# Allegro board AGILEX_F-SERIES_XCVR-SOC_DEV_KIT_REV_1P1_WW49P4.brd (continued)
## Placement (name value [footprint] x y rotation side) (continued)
C966  DNI  [7343-V_LOW-PROFILE]  51.92 195.07 270 bottom
C967  47uF  [7343-V_LOW-PROFILE]  46.71 195.2 270 top
C968  47uF  [7343-V_LOW-PROFILE]  59.16 195.33 270 top
C969  47uF  [7343-V_LOW-PROFILE]  56.84 211.96 90 top
C970  0.022uF  [0402]  50.26 192.53 90 top
C976  100uF  [1206]  215.26 183.82 270 top
C977  100uF  [1206]  212.29 183.82 270 top
C978  100uF  [1206]  215.32 183.85 270 bottom
C979  100uF  [1206]  215.65 195.2 90 top
C980  100uF  [1206]  198.09 185.85 270 bottom
C981  100uF  [1206]  201.17 185.04 0 top
C982  100uF  [1206]  191.41 197.41 90 top
C983  100uF  [1206]  194.28 197.38 90 top
C984  470uF  [7343P]  214.4 196.27 90 bottom
C985  470uF  [7343P]  191.72 197.03 90 bottom
C986  1uF  [0603]  43.36 23.75 0 top
C987  DNI  [0402]  191.13 188.09 0 bottom
C988  2.2uF  [0402]  195.71 198.58 90 bottom
C989  22uF  [1206]  201.68 209.93 0 bottom
C990  22uF  [1206]  207.04 210.69 180 top
C991  22uF  [1206]  201.42 206.58 0 bottom
C992  22uF  [1206]  207.52 204.85 180 bottom
C993  22uF  [1206]  207.52 207.65 180 top
C994  22uF  [1206]  201.29 213.11 0 bottom
C995  22uF  [1206]  207.52 207.65 180 bottom
C1094  100uF  [1206]  191.95 129.41 90 top
C1095  100uF  [1206]  196.95 118.41 270 top
C1096  100uF  [1206]  196.95 118.44 270 bottom
C1097  100uF  [1206]  215.75 118.26 270 bottom
C1098  100uF  [1206]  214.25 129.69 90 top
C1099  100uF  [1206]  212.5 118.29 270 top
C1100  100uF  [1206]  215.72 118.29 270 top
C1101  100uF  [1206]  188.93 129.44 90 top
C1102  470uF  [7343P]  193.57 129.9 90 bottom
C1103  470uF  [7343P]  214.05 130.68 90 bottom
C1104  1uF  [0402]  121.03 111.38 180 bottom
C1105  DNI  [0402]  189.92 122.89 0 bottom
C1107  22uF  [1206]  200.41 144.42 0 bottom
C1108  22uF  [1206]  206.12 139.34 180 bottom
C1109  22uF  [1206]  206.4 145.19 180 top
C1110  22uF  [1206]  200.41 147.83 0 bottom
C1111  22uF  [1206]  206.4 147.83 180 top
C1112  22uF  [1206]  200.41 141.07 0 bottom
C1113  22uF  [1206]  206.4 142.14 180 top
C1116  100uF  [1206]  209.91 153.62 180 bottom
C1117  100uF  [1206]  209.91 156.46 180 top
C1118  100uF  [1206]  209.91 156.46 180 bottom
C1119  100uF  [1206]  209.75 175.67 180 top
C1120  100uF  [1206]  209.91 153.62 180 top
C1121  100uF  [1206]  209.75 175.67 180 bottom
C1122  1uF  [0402]  110.34 118.36 270 bottom
C1123  100uF  [1206]  209.75 178.49 180 bottom
C1124  100uF  [1206]  209.75 178.49 180 top
C1125  DNI  [0402]  193.55 158.93 0 bottom
C1129  150uF  [7343P]  201.55 179.91 0 bottom
C1130  22uF  [1206]  201.5 175.64 180 top
C1131  22uF  [1206]  201.5 175.64 180 bottom
C1132  22uF  [1206]  201.47 153.64 180 top
C1133  22uF  [1206]  201.52 178.56 180 top
C1136  100uF  [1206]  31.65 25.98 0 top
C1137  10uF  [0402]  31.5 28.45 270 top
C1138  22uF  [0603]  23.88 31.37 0 bottom
C1140  150uF  [7343P]  23.62 27.3 0 bottom
C1141  150uF  [7343P]  23.67 27.36 0 top
C1145  100uF  [1206]  125.09 13.87 270 top
C1146  10uF  [0402]  127.3 13.82 180 top
C1148  22uF  [0603]  129.26 21.84 270 bottom
C1149  150uF  [7343P]  125.2 21.67 270 bottom
C1150  150uF  [7343P]  125.22 21.67 270 top
C1154  100uF  [1206]  14.15 29.13 0 top
C1155  10uF  [0402]  14.12 31.52 270 top
C1156  22uF  [0603]  6.48 34.42 0 bottom
C1157  150uF  [7343P]  6.22 30.35 0 top
C1158  150uF  [7343P]  6.22 30.35 0 bottom
C1169  100uF  [1206]  49.05 28.27 0 top
C1170  10uF  [0402]  48.77 30.61 270 top
C1171  22uF  [0603]  41.15 33.53 0 bottom
C1172  150uF  [7343P]  40.89 29.41 0 top
C1173  150uF  [7343P]  40.89 29.46 0 bottom
C1178  10uF  [0603]  62.1 145.41 180 top
C1179  10uF  [0603]  62.1 143 180 top
C1181  47uF  [0603]  60.43 133.68 0 top
C1182  47uF  [0603]  60.41 135.87 0 top
C1184  47uF  [0603]  52.73 49.15 270 top
C1185  10uF  [0603]  57.73 42.62 0 top
C1186  47uF  [0603]  55.14 49.15 270 top
C1187  10uF  [0603]  57.73 45.16 0 top
C1199  100uF  [1206]  100.18 13.92 270 top
C1200  10uF  [0402]  102.41 14.22 180 top
C1201  22uF  [0603]  104.52 21.84 270 bottom
C1202  150uF  [7343P]  100.46 21.79 270 bottom
C1203  150uF  [7343P]  100.46 21.79 270 top
C1217  100uF  [1206]  148.29 13.74 270 top
C1218  10uF  [0402]  150.55 13.77 180 top
C1219  22uF  [0603]  152.5 21.84 270 bottom
C1220  150uF  [7343P]  148.44 21.72 270 bottom
C1221  150uF  [7343P]  148.46 21.72 270 top
C1226  100uF  [1206]  80.59 14.12 270 top
C1227  10uF  [0402]  82.63 14.07 180 top
C1228  22uF  [0603]  84.38 21.84 270 bottom
C1229  150uF  [7343P]  80.26 22.1 270 top
C1230  150uF  [7343P]  80.31 22.1 270 bottom
C1237  47uF  [0603]  39.52 11.73 270 top
C1238  47uF  [0603]  37.34 11.81 270 top
C1290  DNI  [1206]  70.87 116.71 180 bottom
C1291  DNI  [1206]  70.87 113.92 180 bottom
C1292  DNI  [1206]  105.52 132.13 90 bottom
C1293  DNI  [1206]  102.72 132.13 90 bottom
C1294  DNI  [1206]  137.51 132.97 90 bottom
C1295  DNI  [1206]  134.72 132.97 90 bottom
C1296  22uF  [0603]  147.17 120.27 180 bottom
C1297  22uF  [0603]  147.17 117.98 180 bottom
C1298  22uF  [0603]  147.17 124.84 180 bottom
C1299  22uF  [0603]  147.17 122.55 180 bottom
C1300  22uF  [0603]  136.25 125.35 270 bottom
C1301  22uF  [0603]  138.15 125.35 270 bottom
C1302  22uF  [0603]  71.75 125.22 0 bottom
C1303  22uF  [0603]  71.75 123.19 0 bottom
C1304  22uF  [0603]  71.75 119.13 0 bottom
C1305  22uF  [0603]  71.75 121.16 0 bottom
C1306  22uF  [0603]  93.22 126.62 270 bottom
C1307  22uF  [0603]  91.19 126.62 270 bottom
C1308  22uF  [0603]  89.15 126.62 270 bottom
C1309  22uF  [0603]  87.12 126.62 270 bottom
C1310  22uF  [0603]  85.09 126.62 270 bottom
C1316  DNI  [2012]  80.74 93.1 0 bottom
C1317  DNI  [2012]  80.74 89.6 0 bottom
C1318  DNI  [2012]  80.74 91.35 0 bottom
C1319  4.7uF  [0603]  122.15 76.07 270 bottom
C1325  DNI  [0402]  132.52 7.18 180 bottom
C1326  DNI  [0402]  131.64 7.18 180 bottom
C1327  DNI  [0402]  185.83 63.24 0 bottom
C1328  0.1uF  [0402]  166.5 42.67 90 bottom
C1329  1uF  [0402]  166.5 43.69 90 bottom
C1330  0.1uF  [0402]  166.27 45.36 0 bottom
C1331  0.1uF  [0402]  185.39 51.94 0 bottom
C1332  0.1uF  [0402]  177.9 72.77 90 top
C1333  10uF  [C0805]  172.18 75.37 180 top
C1334  10uF  [C0805]  174.6 75.37 180 top
C1335  0.1uF  [0402]  170.53 74.87 0 top
C1336  0.1uF  [0402]  172.06 60.07 270 top
C1337  DNI  [0201]  104.83 95.85 30 bottom
C1338  DNI  [0201]  119.55 103.35 210 bottom
C1339  DNI  [0201]  111.76 95.85 30 bottom
C1340  DNI  [0201]  103.1 104.85 30 bottom
C1341  DNI  [0201]  103.1 103.85 30 bottom
C1342  DNI  [0201]  103.1 102.85 30 bottom
C1343  DNI  [0201]  103.1 101.85 30 bottom
C1344  DNI  [0201]  117.82 107.35 210 bottom
C1345  DNI  [0201]  112.63 107.35 210 bottom
C1346  DNI  [0201]  116.09 107.35 210 bottom
C1347  DNI  [0201]  107.43 94.35 210 bottom
C1348  DNI  [0201]  120.42 109.85 30 bottom
C1349  DNI  [0201]  114.36 96.35 210 bottom
C1350  DNI  [0201]  103.1 105.85 30 bottom
C1351  DNI  [0201]  104.83 99.85 30 bottom
C1352  DNI  [0201]  104.83 101.85 30 bottom
C1353  DNI  [0201]  104.83 103.85 30 bottom
C1354  DNI  [0201]  104.83 105.85 30 bottom
C1355  DNI  [0201]  102.23 107.35 210 bottom
C1356  DNI  [0201]  110.03 95.85 30 bottom
C1357  DNI  [0201]  103.1 106.85 30 bottom
C1358  DNI  [0201]  107.43 107.35 210 bottom
C1359  DNI  [0201]  103.1 94.85 30 bottom
C1360  DNI  [0201]  109.16 107.35 210 bottom
C1361  DNI  [0201]  103.1 100.85 30 bottom
C1362  DNI  [0201]  103.1 97.85 30 bottom
C1363  DNI  [0201]  103.1 99.85 30 bottom
C1364  DNI  [0201]  103.1 96.85 30 bottom
C1365  DNI  [0201]  103.97 94.35 210 bottom
C1366  DNI  [0201]  104.83 97.85 30 bottom
C1367  DNI  [0201]  119.55 97.35 210 bottom
C1368  DNI  [0201]  119.55 98.35 210 bottom
C1369  DNI  [0201]  119.55 99.35 210 bottom
C1370  DNI  [0201]  119.55 100.35 210 bottom
C1371  DNI  [0201]  119.55 101.35 210 bottom
C1372  DNI  [0201]  119.55 102.35 210 bottom
C1373  DNI  [0201]  119.55 104.35 210 bottom
C1374  DNI  [0201]  119.55 105.35 210 bottom
C1375  DNI  [0201]  119.55 106.35 210 bottom
C1376  DNI  [0201]  119.55 107.35 210 bottom
C1377  1uF  [0201]  100.08 104.65 270 bottom
C1378  10uF  [0603]  97.13 75.06 90 bottom
C1379  10uF  [0603]  103.64 125.22 270 bottom
C1380  10uF  [0603]  106.78 125.22 270 bottom
C1381  4.7uF  [0201]  107.43 110.85 150 bottom
C1382  4.7uF  [0201]  107.43 92.35 210 bottom
C1383  4.7uF  [0201]  110.03 111.35 330 bottom
C1384  4.7uF  [0201]  110.89 110.35 210 bottom
C1385  1uF  [0201]  116.09 92.35 210 bottom
C1386  4.7uF  [0201]  109.16 92.35 210 bottom
C1387  4.7uF  [0201]  110.03 91.85 30 bottom
C1388  1uF  [0201]  111.76 91.85 30 bottom
C1389  10uF  [0603]  102.84 74.93 90 bottom
C1390  0.1uF  [0402]  184.33 170.47 180 bottom
C1391  0.1uF  [0402]  185.6 170.47 180 bottom
C1392  0.1uF  [0402]  186.87 170.47 180 bottom
C1393  0.1uF  [0402]  188.14 170.47 180 bottom
C1394  0.1uF  [0402]  189.41 170.47 180 bottom
C1395  0.1uF  [0402]  190.68 170.47 180 bottom
C1396  0.1uF  [0402]  191.95 170.47 180 bottom
C1397  0.1uF  [0402]  193.22 170.47 180 bottom
C1398  0.1uF  [0402]  138.18 194.94 0 bottom
C1399  0.1uF  [0402]  142.62 194.94 0 bottom
C1400  0.1uF  [0402]  147.07 194.94 0 bottom
C1401  0.1uF  [0402]  151.36 194.88 0 bottom
C1402  0.1uF  [0402]  155.96 194.94 0 bottom
C1403  0.1uF  [0402]  160.4 194.94 0 bottom
C1404  0.1uF  [0402]  164.85 194.94 0 bottom
C1405  0.1uF  [0402]  169.16 194.94 0 bottom
C1408  DNI  [0402]  30.71 188.47 90 bottom
C1409  0.1uF  [0402]  33.75 153.42 90 bottom
C1410  0.1uF  [0402]  163.17 125.86 90 top
C1411  0.1uF  [0402]  163.17 127.13 90 top
C1412  10uF  [0603]  33.86 156.01 270 top
C1413  0.1uF  [0402]  35.63 157.76 180 top
C1414  0.1uF  [0402]  36.65 157.76 180 top
C1415  10uF  [0603]  59.2 150.16 90 top
C1416  0.1uF  [0402]  56.64 147.52 0 top
C1417  0.1uF  [0402]  57.68 147.52 0 top
C1424  22uF  [0805]  148.84 93.85 180 bottom
C1425  47uF  [0805]  151.38 93.85 180 bottom
C1426  100uF  [0805]  154.31 93.85 180 bottom
C1427  1uF  [0402]  113.59 60.22 90 bottom
C1428  1uF  [0402]  127.23 55.12 0 bottom
C1429  1uF  [0402]  115.42 59.89 180 bottom
C1430  1uF  [0402]  126.29 63.19 0 bottom
C1431  1uF  [0402]  129 51.55 180 bottom
C1432  1uF  [0402]  124.51 63.32 0 bottom
C1433  1uF  [0402]  124.69 55.12 0 bottom
C1434  1uF  [0402]  129.08 63.22 0 bottom
C1435  1uF  [0402]  127.84 63.22 0 bottom
C1436  1uF  [0402]  123.04 63.32 0 bottom
C1437  1uF  [0402]  121.79 63.32 0 bottom
C1438  1uF  [0402]  118.64 59.79 180 bottom
C1439  1uF  [0402]  116.89 59.89 180 bottom
C1440  1uF  [0402]  118.21 51.05 180 bottom
C1441  47uF  [0805]  126.06 46.99 180 bottom
C1442  47uF  [0805]  103.88 46.79 180 bottom
C1443  47uF  [0805]  108.58 46.79 180 bottom
C1444  47uF  [0805]  106.17 46.79 180 bottom
C1445  47uF  [0805]  119.48 46.99 180 bottom
C1446  47uF  [0805]  111 46.79 180 bottom
C1447  47uF  [0805]  121.64 46.99 180 bottom
C1448  47uF  [0805]  117.45 46.99 180 bottom
C1457  1uF  [0402]  91.29 50.8 270 bottom
C1458  1uF  [0402]  91.29 49.66 270 bottom
C1461  47uF  [0805]  87.35 51.69 0 bottom
C1463  2.2uF  [0402]  90.4 61.09 270 bottom
C1466  1uF  [0402]  84.35 60.83 90 bottom
C1468  1uF  [0402]  102.71 143.32 90 bottom
C1469  1uF  [0402]  103.18 145.24 180 bottom
C1470  1uF  [0402]  103.18 147 180 bottom
C1471  1uF  [0402]  97.89 145.67 90 bottom
C1472  1uF  [0402]  102.78 152.92 90 bottom
C1473  1uF  [0402]  95.48 153.92 90 bottom
C1474  1uF  [0402]  95.98 149.22 180 bottom
C1475  1uF  [0402]  95.91 142.84 180 bottom
C1476  1uF  [0402]  91.36 143.32 90 bottom
C1477  1uF  [0402]  91.76 145.24 180 bottom
C1478  1uF  [0402]  91.76 147 180 bottom
C1479  1uF  [0402]  84.09 153.94 90 bottom
C1480  1uF  [0402]  91.36 152.92 90 bottom
C1481  1uF  [0402]  86.53 145.72 90 bottom
C1482  1uF  [0402]  84.55 149.22 180 bottom
C1483  1uF  [0402]  84.55 142.87 180 bottom
C1484  10uF  [0603]  119.23 140.65 180 bottom
C1485  10uF  [0603]  96.43 140.65 180 bottom
C1486  10uF  [0603]  85.03 140.65 180 bottom
C1487  10uF  [0603]  99.78 142.92 270 bottom
C1488  10uF  [0603]  88.27 142.92 270 bottom
C1489  1uF  [0402]  102.74 141.73 90 bottom
C1490  1uF  [0402]  95.48 155.32 90 bottom
C1491  1uF  [0402]  95.48 152.91 90 bottom
C1492  1uF  [0402]  104.78 141.73 270 bottom
C1493  1uF  [0402]  84.05 155.32 90 bottom
C1494  1uF  [0402]  84.09 152.87 90 bottom
C1495  1uF  [0402]  93.34 141.73 270 bottom
C1496  1uF  [0402]  91.31 141.73 90 bottom
C1497  10uF  [0603]  103.51 139.72 0 bottom
C1498  10uF  [0603]  91.91 139.72 0 bottom
C1499  1uF  [0402]  125.63 143.32 90 bottom
C1500  1uF  [0402]  126.08 145.24 180 bottom
C1501  1uF  [0402]  118.85 142.82 180 bottom
C1502  1uF  [0402]  126.08 147 180 bottom
C1503  1uF  [0402]  118.36 149.76 90 bottom
C1504  1uF  [0402]  126.01 153.37 0 bottom
C1505  1uF  [0402]  118.34 147.17 90 bottom
C1506  1uF  [0402]  118.34 153.8 90 bottom
C1507  1uF  [0402]  114.21 152.92 90 bottom
C1508  1uF  [0402]  106.9 147.32 90 bottom
C1509  1uF  [0402]  114.63 147 180 bottom
C1510  1uF  [0402]  114.21 143.32 90 bottom
C1511  1uF  [0402]  114.63 145.24 180 bottom
C1512  1uF  [0402]  107.43 142.84 180 bottom
C1513  1uF  [0402]  107.41 149.22 180 bottom
C1514  1uF  [0402]  106.91 153.8 90 bottom
C1515  10uF  [0603]  122.65 146.81 270 bottom
C1516  10uF  [0603]  122.71 142.92 270 bottom
C1517  10uF  [0603]  111.25 142.92 270 bottom
C1518  10uF  [0603]  110.84 146.81 270 bottom
C1519  10uF  [0603]  107.91 140.65 180 bottom
C1520  1uF  [0402]  127.64 141.73 270 bottom
C1521  1uF  [0402]  125.6 141.73 90 bottom
C1522  1uF  [0402]  118.34 155.32 90 bottom
C1523  1uF  [0402]  118.34 152.78 90 bottom
C1524  1uF  [0402]  106.91 155.32 90 bottom
C1525  1uF  [0402]  106.91 152.78 90 bottom
C1526  1uF  [0402]  114.17 141.73 90 bottom
C1527  1uF  [0402]  116.2 141.73 270 bottom
C1528  10uF  [0603]  125.91 139.72 0 bottom
C1529  10uF  [0603]  114.71 139.97 0 bottom
C1530  1uF  [0402]  80.74 149.1 180 bottom
C1531  1uF  [0402]  73.12 149.22 180 bottom
C1532  1uF  [0402]  74.35 147.32 270 bottom
C1533  1uF  [0402]  80.31 145.22 180 bottom
C1534  1uF  [0402]  79.91 152.92 90 bottom
C1535  1uF  [0402]  72.62 153.8 90 bottom
C1536  1uF  [0402]  75.11 145.72 90 bottom
C1537  1uF  [0402]  80.31 146.97 180 bottom
C1546  10uF  [0603]  71.88 147.7 270 bottom
C1547  10uF  [0603]  72.24 140.08 90 bottom
C1551  1uF  [0402]  81.92 141.73 270 bottom
C1552  1uF  [0402]  79.91 141.72 90 bottom
C1553  1uF  [0402]  69.95 153.54 90 bottom
C1554  1uF  [0402]  72.62 152.78 90 bottom
C1559  10uF  [0603]  81.53 139.32 90 bottom
C1560  10uF  [0603]  69.91 154.92 0 bottom
C1561  1uF  [0402]  133.99 142.49 270 bottom
C1562  1uF  [0402]  133.99 143.76 270 bottom
C1563  1uF  [0402]  133.99 145.03 270 bottom
C1564  1uF  [0402]  133.99 155.57 270 bottom
C1565  1uF  [0402]  133.99 146.3 270 bottom
C1566  1uF  [0402]  133.99 147.45 270 bottom
C1567  1uF  [0402]  133.99 150.5 270 bottom
C1568  1uF  [0402]  133.99 151.76 270 bottom
C1569  1uF  [0402]  133.99 153.03 270 bottom
C1570  1uF  [0402]  133.99 154.31 270 bottom
C1571  1uF  [0402]  128.65 160.45 180 top
C1572  1uF  [0402]  125.02 160.45 180 top
C1573  1uF  [0402]  133.99 145.03 90 top
C1574  1uF  [0402]  126.16 160.45 180 top
C1575  1uF  [0402]  123.98 160.45 180 top
C1576  1uF  [0402]  133.99 147.45 90 top
C1577  1uF  [0402]  133.99 150.5 90 top
C1578  1uF  [0402]  122.91 160.45 180 top
C1579  1uF  [0402]  133.99 153.03 90 top
C1580  1uF  [0402]  120.68 160.43 180 top
C1581  10uF  [0603]  134.09 140.84 180 bottom
C1582  10uF  [0603]  134.09 148.87 180 bottom
C1583  10uF  [0603]  129.16 142.9 0 bottom
C1584  10uF  [0603]  134.09 157.15 180 bottom
C1585  10uF  [0603]  134.08 157.23 180 top
C1586  47uf  [1206]  67.28 99.06 180 bottom
C1587  10uF  [0603]  36.62 146.33 270 top
C1588  0.1uF  [0402]  54.99 158.04 0 top
C1589  100pF  [0402]  170.43 108.48 90 top
C1590  1uF  [0402]  170.41 135.25 90 top
C1591  1uF  [0402]  164.44 130.94 0 top
C1592  1uF  [0402]  168.5 130.94 0 top
C1593  150uF  [7343P]  194.79 17.91 180 bottom
C1594  150uF  [7343P]  194.79 17.91 180 top
C1595  0.1uF  [0402]  149.32 209.55 90 bottom
C1596  10uF  [1206]  153.29 200.15 270 bottom
C1597  0.1uF  [0402]  155.57 201.29 0 bottom
C1598  47uF  [7343-V_LOW-PROFILE]  194.54 7.37 180 top
C1599  47uF  [7343-V_LOW-PROFILE]  194.54 7.37 180 bottom
C1600  DNI  [C0805]  158.47 78.23 90 top
C1609  1uF  [0402]  125.93 55.12 0 bottom
C1610  1uF  [0402]  123.06 51.41 180 bottom
C1611  1uF  [0402]  121.61 51.41 180 bottom
C1612  100uF  [1206]  15.65 152.53 180 top
C1613  10uF  [0402]  16.66 149.81 90 top
C1614  22uF  [0603]  31.19 139.09 90 top
C1615  150uF  [7343P]  23.57 152.2 180 top
C1616  150uF  [7343P]  23.57 152.22 180 bottom
C1622  1uF  [0402]  163.01 132.56 180 bottom
C1623  22uF  [0603]  123.7 96.65 180 bottom
C1624  22uF  [0603]  152.4 127.76 270 bottom
C1625  22uF  [0603]  126.87 97.16 0 bottom
C1626  22uF  [0603]  150.37 127.76 270 bottom
C1627  100uF  [0805]  156.46 126.62 90 bottom
C1628  0.1uF  [0402]  125.6 90.81 120 bottom
C1629  150uF  [2917]  131.51 211.28 270 top
C1636  10pF  [0402]  79.77 207.59 180 top
C1637  DNI  [0402]  77.67 215.32 0 top
C1650  10uF  [0603]  87.48 202.11 90 top
C1652  1uF  [0402]  85.78 203 180 top
C1660  100uF  [0805]  83.82 179.07 270 bottom
C1661  100uF  [0805]  83.82 179.07 90 top
C1664  470uF  [2917]  85.06 169.88 0 top
C1665  22uF  [0805]  79.78 196.72 180 top
C1666  22uF  [0805]  94.41 200.79 270 top
C1667  22uF  [0805]  93.85 195.58 0 bottom
C1668  22uF  [0805]  89.51 204.85 90 top
C1669  1uF  [0402]  92.08 195.86 0 top
C1670  1uF  [0402]  81.58 196.75 0 top
C1682  100uF  [0805]  104.78 178.92 90 bottom
C1683  100uF  [0805]  104.78 178.92 270 top
C1687  470uF  [2917]  103.05 169.88 180 top
C1688  1uF  [0402]  95.61 196.24 0 top
C1689  1uF  [0402]  106.3 195.58 0 top
C1690  22uF  [0805]  108.03 195.45 0 bottom
C1691  22uF  [0805]  108.15 200.79 270 top
C1692  22uF  [0805]  103.3 204.85 90 top
C1693  22uF  [0805]  81.53 205.26 270 top
C1703  100uF  [0805]  110.52 179.07 90 top
C1704  100uF  [0805]  110.52 179.07 270 bottom
C1709  470uF  [2917]  112.75 169.85 0 bottom
C1711  1uF  [0402]  119.96 195.63 0 top
C1712  1uF  [0402]  109.58 195.68 0 top
C1713  22uF  [0805]  81.53 202.87 270 top
C1714  22uF  [0805]  121.16 201.29 270 top
C1715  22uF  [0805]  117.2 204.85 90 top
C1716  22uF  [0805]  121.36 195.45 0 bottom
C1718  0.1uF  [0402]  69.19 208.76 90 top
C1719  330pF  [0603]  82.65 207.92 0 bottom
C1720  100pF  [0402]  81.18 209.4 270 top
C1721  2200pF  [0402]  81.16 211.13 90 top
C1726  100uF  [0805]  132.03 178.92 90 bottom
C1727  100uF  [0805]  132.03 178.92 270 top
C1733  470uF  [2917]  129.97 169.9 180 top
C1734  1uF  [0402]  122.48 195.86 0 top
C1735  1uF  [0402]  133.17 195.5 0 top
C1736  22uF  [0805]  79.78 196.72 0 bottom
C1737  22uF  [0805]  130.68 201.55 270 bottom
C1738  22uF  [0805]  130.18 204.85 90 top
C1739  22uF  [0805]  134.85 195.28 0 bottom
C1743  100uF  [7343P]  172.9 186.79 270 bottom
C1774  22uF  [0603]  80.77 44.55 0 top
C1775  22uF  [0603]  83.16 50.44 270 bottom
C1776  22uF  [0603]  83.16 50.44 270 top
C1777  0.1uF  [0402]  75.72 52.96 270 top
C1779  1000pF  [0402]  113.28 48.13 90 bottom
C1780  4.7uF  [0402]  76.2 48.01 0 top
C1781  22uF  [0603]  146.02 146.02 90 top
C1782  1000pF  [0402]  115.19 156.84 0 bottom
C1783  22uF  [0603]  142.37 148.46 0 top
C1784  1uF  [0402]  142.24 146.69 90 top
C1786  4.7uF  [0402]  144.27 142.11 90 top
C1788  22uF  [1206]  144.91 187.83 0 top
C1789  22uF  [1206]  167.39 183.92 180 top
C1790  DNI  [1206]  167.39 186.72 180 bottom
C1791  22uF  [1206]  144.91 190.88 0 top
C1792  DNI  [1206]  144.91 187.83 0 bottom
C1793  22uF  [1206]  144.88 184.99 0 top
C1794  DNI  [1206]  144.91 190.88 0 bottom
C1795  22uF  [1206]  167.39 186.74 180 top
C1796  100uF  [7343P]  172.9 186.79 270 top
C1798  100uF  [1206]  165.81 168 270 bottom
C1799  100uF  [1206]  160.15 168.02 270 top
C1801  470uF  [2917]  153.54 169.16 90 bottom
C1802  470uF  [2917]  138.91 169.19 90 bottom
C1803  100uF  [1206]  151.76 168.02 270 top
C1804  100uF  [1206]  154.56 168.02 270 top
C1805  100uF  [1206]  157.35 168.02 270 top
C1807  470uF  [2917]  148.46 169.16 90 bottom
C1808  470uF  [2917]  158.62 169.16 90 bottom
C1809  100uF  [1206]  162.94 168.02 270 bottom
C1810  100uF  [1206]  162.94 168.02 270 top
C1811  100uF  [1206]  165.74 168.02 270 top
C1812  100uF  [1206]  148.97 168.02 270 top
C1813  100uF  [1206]  146.18 168.02 270 top
C1814  1uF  [0402]  81.51 50.57 0 top
C1815  22uF  [0603]  142.37 150.75 0 top
C1817  10uF  [0603]  178.18 206.38 0 top
C1827  0.01uF  [0402]  183.14 196.06 180 top
C1840  22uF  [0603]  80.77 46.58 0 top
C1842  22uF  [0603]  148.31 146.08 90 top
C1843  0.1uF  [0402]  139.19 140.21 0 top
C1844  150uF  [2917]  107.67 211.15 270 top
C1845  22uF  [1206]  67.31 207.54 270 bottom
C1846  22uF  [1206]  64.26 207.49 270 top
C1847  22uF  [1206]  64.29 207.47 270 bottom
C1848  2.2uF  [0402]  67.49 210.72 270 top
C1858  0.1uF  [0402]  21.44 56.97 180 bottom
C1859  0.1uF  [0402]  24.64 56.97 180 bottom
C1860  0.1uF  [0402]  25.7 56.97 180 bottom
C1861  0.1uF  [0402]  28.91 56.97 180 bottom
C1862  0.1uF  [0402]  31.5 56.62 90 bottom
C1863  0.1uF  [0402]  31.5 55.02 90 bottom
C1864  0.1uF  [0402]  31.5 53.95 90 bottom
C1865  0.1uF  [0402]  31.5 52.35 90 bottom
C1866  0.1uF  [0402]  31.5 51.28 90 bottom
C1867  0.1uF  [0402]  31.5 49.68 90 bottom
C1868  0.1uF  [0402]  31.5 48.59 90 bottom
C1869  0.1uF  [0402]  31.5 46.99 90 bottom
C1870  0.1uF  [0402]  28.45 47.09 90 bottom
C1871  0.1uF  [0402]  26.7 47.09 270 bottom
C1872  0.1uF  [0402]  24.89 47.09 90 bottom
C1873  0.1uF  [0402]  23.09 47.09 270 bottom
C1874  0.1uF  [0402]  12.14 140.49 0 top
C1879  47uF  [0805]  162.38 77.67 270 bottom
C1880  22uF  [0805]  162.38 75.44 270 bottom
C1881  22uF  [0805]  154.03 77.83 90 bottom
C1895  1uF  [0402]  180.01 203.1 0 bottom
C1896  150uF  [7343P]  195.96 210.9 90 top
C1899  100pF  [0402]  210.67 184.94 270 bottom
C1900  1nF  [0402]  210.67 183.54 270 bottom
C1901  150uF  [7343P]  196.6 147.83 90 top
C1921  2.2uF  [0402]  195.96 138.38 0 bottom
C1922  1nF  [0402]  208.2 114.6 180 bottom
C1923  22pF  [0402]  206.86 114.6 0 bottom
C1931  0.1uF  [0402]  81.03 48.26 90 top
C1934  0.1uF  [0402]  144.32 146.25 180 top
C1937  DNI  [0402]  24.97 40.08 90 bottom
C1939  DNI  [0402]  137.97 20.75 0 bottom
C1941  DNI  [0402]  7.57 43.13 90 bottom
C1943  DNI  [0402]  27.99 127 180 bottom
C1945  DNI  [0402]  42.24 42.24 90 bottom
C1946  100pF  [0402]  28.74 43.1 270 bottom
C1947  100pF  [0402]  142.72 18.82 270 bottom
C1948  100pF  [0402]  14.48 46.23 0 bottom
C1949  100pF  [0402]  24.99 120.35 180 bottom
C1950  100pF  [0402]  38.1 46.3 0 bottom
C1951  100pF  [0402]  117.14 17.07 180 bottom
C1953  DNI  [0402]  113.23 20.75 0 bottom
C1954  100pF  [0402]  163.19 17.49 180 bottom
C1956  DNI  [0402]  161.21 20.75 0 bottom
C1957  100pF  [0402]  96.01 17.08 180 bottom
C1959  DNI  [0402]  93.09 20.75 0 bottom
C1960  DNI  [0603]  145.57 177.77 270 bottom
C1961  1nF  [0402]  181.46 164.49 270 top
C1962  33pF  [0402]  181.48 165.79 90 top
C1966  100pF  [0402]  197.03 171.28 0 bottom
C1967  2.2nF  [0402]  195.81 168.05 90 bottom
C1970  1uF  [0402]  61.49 140.21 180 top
C1975  0.01uF  [0402]  64.8 53.57 270 top
C1976  100pF  [0402]  64.59 49.35 270 top
C1978  1uF  [0402]  99.52 202.34 90 top
C1979  10uF  [0603]  101.57 201.6 90 top
C1997  1uF  [0402]  113.31 202.03 90 top
C1998  10uF  [0603]  115.37 201.5 90 top
C2000  2.2uF  [0402]  70.02 212.82 180 top
C2001  2.2uF  [0402]  70.1 214.95 180 top
C2002  4.7uF  [0402]  70.06 211.07 270 top
C2016  1uF  [0402]  125.43 202.03 90 top
C2017  10uF  [0603]  127.64 201.35 90 top
C2044  47uf  [1206]  182.78 207.09 0 top
C2045  47uf  [1206]  182.78 207.09 0 bottom
C2047  100pF  [0402]  186.18 200.66 270 top
C2048  10uF  [0603]  178.18 208.53 0 top
C2062  1uF  [0402]  50.29 11.94 180 top
C2063  2.2uF  [0402]  175.15 162.7 180 bottom
C2064  100uF  [1206]  209.88 150.75 180 bottom
C2065  100uF  [1206]  209.88 150.75 180 top
C2066  100uF  [1206]  215.34 178.38 90 bottom
C2067  100uF  [1206]  215.24 178.41 90 top
C2068  150uF  [2917]  56.85 211.94 270 bottom
C2069  150uF  [2917]  120.63 211.15 270 top
C2070  150uF  [2917]  92.78 211.15 270 top
C2076  100pF  [0402]  53.52 134.39 180 top
C2079  0.01uF  [0402]  53.29 141.91 180 bottom
C2086  1uF  [0402]  55.07 54.81 0 top
C2091  100pF  [0402]  39.73 18.08 0 top
C2094  0.01uF  [0402]  42.8 19.38 0 top
C2095  10uF  [0603]  46.02 10.46 0 top
C2096  10uF  [0603]  46.05 11.51 0 bottom
C2097  22pF  [0402]  184.73 196.06 0 top
C2098  22pF  [0402]  41.38 19.3 180 top
C2099  22pF  [0402]  62.33 49.91 90 bottom
C2100  22pF  [0402]  54.51 138.43 270 bottom
C2101  DNI  [0603]  166.12 175.82 270 bottom
C2108  22pF  [0402]  60.5 179.93 180 top
C2110  1uF  [0402]  72.54 178.97 90 top
C2113  1uF  [0402]  75.35 203 180 top
C2114  0.47uF  [0402]  71.45 202.97 0 top
C2115  0.47uF  [0402]  74.12 203 180 bottom
C2116  0.47uF  [0402]  78.38 202.95 0 bottom
C2117  0.47uF  [0402]  76.58 203 180 bottom
C2118  DNI  [0402]  83.52 210.97 90 top
C2119  470uF  [2917]  85.06 169.9 0 bottom
C2120  100uF  [0805]  83.82 174.73 90 top
C2121  100uF  [0805]  83.82 174.73 270 bottom
C2122  470uF  [2917]  103.02 169.9 180 bottom
C2123  100uF  [0805]  104.75 174.7 90 bottom
C2124  100uF  [0805]  104.72 174.7 270 top
C2125  470uF  [2917]  112.75 169.85 0 top
C2126  100uF  [0805]  111.18 174.73 90 top
C2127  100uF  [0805]  111.18 174.73 270 bottom
C2128  470uF  [2917]  129.97 169.88 180 bottom
C2129  100uF  [0805]  131.8 174.78 270 top
C2130  100uF  [0805]  131.8 174.78 90 bottom
C2131  47pF  [0402]  89.53 200.41 90 bottom
C2132  47pF  [0402]  81.33 199.62 0 bottom
C2133  47pF  [0402]  104.39 199.61 0 bottom
C2134  47pF  [0402]  96.72 199.16 0 bottom
C2135  47pF  [0402]  118.21 199.78 0 bottom
C2136  47pF  [0402]  110.49 199.21 0 bottom
C2137  47pF  [0402]  131.7 198.64 270 bottom
C2138  47pF  [0402]  122.25 199.44 0 bottom
CN1  CN-USB  [USB-67068-8001]  11.69 172.09 270 top
CON1  2309407-5  [SODIMM_DDR4_260]  123.44 57.4 0 top
D1  LT1389ACS8-1.25#PBF  [SOIC-8]  155.81 71.25 0 top
D2  LED_WE1206  [WE_LED1206]  25.78 7.35 270 top
D3  LED_WE1206  [WE_LED1206]  29.08 7.35 270 top
D4  LED_WE1206  [WE_LED1206]  32.38 7.35 270 top
D5  LED_WE1206  [WE_LED1206]  35.68 7.35 270 top
D6  LED_WE1206  [WE_LED1206]  38.98 7.35 270 top
D7  LED_WE1206  [WE_LED1206]  184.28 212.98 90 top
D8  LED_WE1206  [WE_LED1206]  180.97 212.98 90 top
D9  LED_WE1206  [WE_LED1206]  177.67 212.98 90 top
D10  LED_WE1206  [WE_LED1206]  174.37 212.98 90 top
D11  Red_LED  [WE_LED1206]  171.07 212.98 90 top
D12  Red_LED  [WE_LED1206]  167.77 212.98 90 top
D13  Amber_LED  [WE_LED1206]  164.47 212.98 90 top
D14  Amber_LED  [WE_LED1206]  161.16 212.98 90 top
D15  LED_WE1206  [WE_LED1206]  139.45 212.98 90 top
D16  LED_WE1206  [WE_LED1206]  136.4 212.98 90 top
D17  LED_WE1206  [WE_LED1206]  142.49 212.98 90 top
D18  LED_WE1206  [WE_LED1206]  145.54 212.98 90 top
D19  LED_WE1206  [WE_LED1206]  154.69 212.98 90 top
D20  LED_WE1206  [WE_LED1206]  157.73 212.98 90 top
D23  Red_LED  [WE_LED1206]  148.59 212.98 90 top
D24  Red_LED  [WE_LED1206]  151.64 212.98 90 top
D27  LED_WE1206  [WE_LED1206]  174.37 146.3 90 top
D28  LED_WE1206  [WE_LED1206]  177.42 146.3 90 top
D29  LED_WE1206  [WE_LED1206]  180.47 146.3 90 top
D30  LED_WE1206  [WE_LED1206]  183.51 146.3 90 top
D33  Amber_LED  [WE_LED1206]  189.61 146.3 90 top
D34  Amber_LED  [WE_LED1206]  192.66 146.3 90 top
D35  SMCJ12A  [DO-214AB]  14.83 187.07 180 top
D36  LED_WE1206  [WE_LED1206]  7.11 186.56 0 top
D37  LED_WE1206  [WE_LED1206]  7.11 184.02 0 top
D38  LED_WE1206  [WE_LED1206]  190.88 212.98 90 top
D39  LED_WE1206  [WE_LED1206]  187.58 212.98 90 top
D40  LED_WE1206  [WE_LED1206]  186.56 146.3 90 top
D41  LT1389BCS8-2.5#PBF  [SOIC-8]  154.79 210.18 270 bottom
FB1  DNI  [805]  154.28 78.23 270 top
FB4  120ohm, 800mA  [805]  96.97 40.64 90 bottom
FB5  120ohm, 800mA  [805]  91.31 40.01 180 bottom
FB6  120ohm, 800mA  [805]  91.95 30.73 90 bottom
FB7  120ohm, 800mA  [805]  157.3 141.58 0 top
FB8  120ohm, 800mA  [805]  160.77 141.58 0 top
FB9  120ohm, 800mA  [805]  173.33 139.45 270 top
FB10  120ohm, 800mA  [805]  159.36 130.94 180 top
FB14  120ohm, 800mA  [805]  173.33 137.29 270 top
FB15  120ohm, 800mA  [805]  23.09 7.24 180 bottom
J1  LTI-SASF546-P26-X1  [SMA_LTI-SASF546-P26-X1]  100.71 6.73 0 top
J2  LTI-SASF546-P26-X1  [SMA_LTI-SASF546-P26-X1]  139.57 6.73 0 top
J3  LTI-SASF546-P26-X1  [SMA_LTI-SASF546-P26-X1]  124.59 6.73 0 top
J4  LTI-SASF546-P26-X1  [SMA_LTI-SASF546-P26-X1]  85.72 6.73 0 top
J5  QSH-030-01-F-D-A  [QSH-030-01-C-D-A]  46.36 152.82 180 top
J6  LTI-SASF546-P26-X1  [SMA_LTI-SASF546-P26-X1]  70.74 36.7 270 top
J7  LTI-SASF546-P26-X1  [SMA_LTI-SASF546-P26-X1]  55.75 36.7 270 top
J10  QTH-030-02-L-D-A  [QTH-030]  187.71 86.36 90 top
J11  QTH-030-02-L-D-A  [QTH-030]  187.71 111.76 90 top
J12  Molex_zQSFP_Connector  [170432-0002]  39.94 93.74 270 top
J13  2x8 MXP  [2X8A_81_MXP-S50-0-4-GENERIC]  44.86 121.34 180 top
J14  -  [10146065-113A0LF]  205.74 57.15 90 top
J15  HFJ11-1G02E  [RJ45]  13.89 19.43 270 top
J16  2X5_100mil  [HDR2X5_100MIL_SMT]  146.91 158.5 270 bottom
J17  2X5_100mil  [HDR2X5_100MIL_SMT]  156.94 134.62 180 bottom
J18  2X5_100mil  [HDR2X5_100MIL_SMT]  24.13 164.97 0 bottom
J19  HDR2X5  [CONN_39_26_7108]  9.7 146.05 90 top
J20  FAN_Conn  [MOLEX_0470533000_TXSI]  182.34 138.56 180 top
J21  DNI  [MOLEX_0470533000_TXSI]  20.29 119.89 0 top
J22  LTI-SASF546-P26-X1  [SMA_LTI-SASF546-P26-X1]  55.75 21.72 90 top
J23  LTI-SASF546-P26-X1  [SMA_LTI-SASF546-P26-X1]  70.74 21.72 90 top
J24  LTI-SASF546-P26-X1  [SMA_LTI-SASF546-P26-X1]  55.75 6.73 90 top
J25  LTI-SASF546-P26-X1  [SMA_LTI-SASF546-P26-X1]  70.74 6.73 90 top
J26  HDR2X10  [HDR2X10_100MIL]  143.48 45.31 270 bottom
J27  SMA  [SMA_LTI-SASF546-P26-X1]  154.56 6.73 0 top
J28  LTI-SASF546-P26-X1  [SMA_LTI-SASF546-P26-X1]  184.53 21.72 180 top
J29  SMA  [SMA_LTI-SASF546-P26-X1]  169.54 6.73 0 top
J30  LTI-SASF546-P26-X1  [SMA_LTI-SASF546-P26-X1]  169.54 21.72 180 top
J31  SMA  [SMA_LTI-SASF546-P26-X1]  184.53 35.43 270 top
J34  SMA  [SMA_LTI-SASF546-P26-X1]  169.54 35.43 180 top
J35  2X5_100mil  [HDR2X5_100MIL_SMT]  162.43 158.5 270 bottom
J37  PCIe 2x3 ATX  [PCIE_2X3_ATX]  3.3 198.88 270 top
J49  2X5_100mil  [HDR2X5_100MIL_SMT]  169.9 134.49 180 bottom
J50  LTI-SASF546-P26-X1  [SMA_LTI-SASF546-P26-X1]  184.53 6.73 0 top
J51  TSW-103-08-G-S  [1X3_HDR_TH]  164.18 147.45 0 top
L1  150nH  [HC_TK0_SM_10800X8000_MA]  87.12 185.67 270 top
L2  3A FB/26Ohm  [IND_0603]  140.56 113.79 270 bottom
L5  3A FB/26Ohm  [IND_0603]  75.16 93.34 0 bottom
L6  3A FB/26Ohm  [IND_0603]  148.05 111.86 270 bottom
L8  120 Ohm, 1A  [0402]  129.77 76.83 90 bottom
L9  120 Ohm, 1A  [0402]  69.06 101.35 0 bottom
L10  1.0uH  [VISHAY_2520]  69.47 72.39 270 top
L11  1.0uH  [VISHAY_2520]  69.47 68.45 90 top
L12  1.0uH  [VISHAY_2520]  39.66 68.58 0 bottom
L13  1.0uH  [IND_WURTH_74479276210]  57.91 94.87 270 top
L14  1.0uH  [IND_WURTH_74479276210]  34.85 93.17 90 bottom
L15  1.0uH  [IND_WURTH_74479276210]  57.91 98.68 270 top
L16  BLM15AG221SN1  [0402]  33.4 159.61 270 bottom
L17  BLM15AG221SN1  [0402]  165.1 84.33 0 bottom
L18  BLM15AG221SN1  [0402]  152.4 35.89 0 bottom
L19  BLM15AG221SN1  [0402]  48.39 104.78 180 bottom
L20  2.5A, 220 Ohm FB  [IND_0603]  173.61 43.95 270 top
L21  2.5A, 220 Ohm FB  [IND_0603]  197.48 67.69 270 bottom
L22  2.5A, 220 Ohm FB  [IND_0603]  171.55 57.78 0 bottom
L23  2.5A, 220 Ohm FB  [IND_0603]  175.49 69.98 0 bottom
L24  2.5A, 220 Ohm FB  [IND_0603]  171.55 56.26 0 bottom
L25  2.5A, 220 Ohm FB  [IND_0603]  178.66 69.98 0 bottom
L26  2.5A, 220 Ohm FB  [IND_0603]  173.35 51.69 90 bottom
L27  2.5A, 220 Ohm FB  [IND_0603]  191.97 69.95 180 bottom
L28  2.5A, 220 Ohm FB  [IND_0603]  197.49 55.63 270 bottom
L29  2.5A, 220 Ohm FB  [IND_0603]  179.68 48.26 90 bottom
L30  2.5A, 220 Ohm FB  [IND_0603]  187.91 69.95 0 bottom
L31  2.5A, 220 Ohm FB  [IND_0603]  197.49 59.69 270 bottom
L32  2.5A, 220 Ohm FB  [IND_0603]  197.49 51.56 270 bottom
L33  2.5A, 220 Ohm FB  [IND_0603]  197.49 63.75 90 bottom
L34  2.5A, 220 Ohm FB  [IND_0603]  175.11 63.25 270 bottom
L35  2.5A, 220 Ohm FB  [IND_0603]  188.57 43.05 180 bottom
L39  0.1uH  [SL1616A]  69.19 110.36 0 bottom
L40  2.5A, 220 Ohm FB  [IND_0603]  178.03 74.42 180 top
L41  0.1uH  [SL1616A]  160.15 104.14 90 bottom
L42  3.5A FB/70Ohm  [IND_0603]  156.08 128.91 180 bottom
L47  150nH  [HC_TK0_SM_10800X8000_MA]  100.46 185.67 270 top
L48  150nH  [HC_TK0_SM_10800X8000_MA]  114.68 185.67 270 top
L49  150nH  [HC_TK0_SM_10800X8000_MA]  128.14 185.67 270 top
L51  22ohm@100Mhz 8A  [0603]  161.42 80.59 90 bottom
MTH3  MT_HOLE_GND  [MTH250R150]  23.5 193.15 0 top
MTH4  MT_HOLE_GND  [MTH250R150]  69.22 193.15 0 top
MTH5  MT_HOLE_GND  [MTH250R150]  46.36 213.98 0 top
NOREF  -  [unnamed]  209.58 -2.57 0 top
NOREF#2  -  [unnamed]  5.08 124.46 0 top
NOREF#3  -  [unnamed]  213.36 213.36 0 top
NOREF#4  -  [unnamed]  111.76 5.08 0 top
NOREF#5  -  [#2]  94.47 177.15 0 top
NOREF#6  -  [#2]  218.22 217.88 0 top
NOREF#7  -  [unnamed]  10.77 214.63 0 top
NOREF#8  -  [#2]  0 0 90 top
NOREF#9  -  [unnamed]  69.19 58.42 0 top
NOREF#10  -  [unnamed#3]  119.82 26.9 0 top
NOREF#11  -  [unnamed]  214.25 11.43 0 top
NOREF#12  -  [unnamed#3]  3.81 -2.54 0 top
NOREF#13  -  [unnamed]  8.89 221.01 0 top
NOREF#14  -  [unnamed]  137.74 68.8 0 top
NOREF#15  -  [unnamed]  101.6 213.36 0 top
NOREF#16  -  [unnamed]  84.54 136.16 0 top
NOREF#17  -  [unnamed#3]  3.81 220.98 0 top
NOREF#18  -  [unnamed]  137.1 137.44 0 top
NOREF#19  -  [unnamed]  205.74 214.63 0 top
NOREF#20  -  [unnamed]  209.58 220.95 0 top
NOREF#21  -  [#2]  0 -5.08 90 top
NOREF#22  -  [#2]  0 218.44 90 top
NOREF#23  -  [unnamed]  213.36 5.08 0 top
NOREF#24  -  [unnamed]  163.17 120.01 0 top
NOREF#25  -  [unnamed]  17.78 3.81 0 top
NOREF#26  -  [unnamed]  5.08 54.19 0 top
NOREF#27  -  [unnamed]  102.72 160.53 0 top
NOREF#28  -  [unnamed#3]  214.63 220.98 0 top
NOREF#29  -  [unnamed]  44.45 5.08 0 top
NOREF#30  -  [unnamed#3]  214.63 -2.54 0 top
NOREF#31  -  [unnamed]  5.08 109.48 0 top
NOREF#32  -  [unnamed]  213.36 110.49 0 top
NOREF#33  -  [unnamed]  5.08 213.36 0 top
NOREF#34  -  [unnamed]  8.89 -2.51 0 top
NOREF#35  -  [#2]  0 217.17 0 top
NOREF#36  -  [unnamed]  85.79 68.66 0 top
NOREF#37  -  [unnamed]  17.78 3.81 180 bottom
NOREF#38  -  [unnamed]  8.89 221.01 180 bottom
NOREF#39  -  [unnamed]  8.89 -2.51 180 bottom
NOREF#40  -  [unnamed]  209.58 220.95 180 bottom
NOREF#41  -  [unnamed]  10.77 214.63 180 bottom
NOREF#42  -  [unnamed]  205.74 214.63 180 bottom
NOREF#43  -  [unnamed]  209.58 -2.57 180 bottom
NOREF#44  -  [unnamed]  214.25 11.43 180 bottom
Q1  MMBT2222A-7-F  [SOT23-BJT]  147.83 89.92 270 bottom
Q2  MMBT2222A-7-F  [SOT23-BJT]  147.04 82.42 270 bottom
Q3  MMBT2222A-7-F  [SOT23-BJT]  147.04 86.23 270 bottom
Q4  FDV305N  [SOT23]  119.24 21.82 270 bottom
Q5  FDV305N  [SOT23]  118.63 15.09 90 bottom
Q6  MMBT3906-7-F  [SOT23-BJT]  48.49 80.75 270 bottom
Q7  FDV305N  [SOT23]  58.93 54.29 0 bottom
R1  DNI  [0402]  143.48 87.63 270 bottom
R2  DNI  [0402]  143.48 82.55 270 bottom
R3  4.70K  [0402]  143.48 86.36 90 bottom
R4  4.70K  [0402]  143.48 81.28 90 bottom
R5  10.0K  [0402]  150.75 90.55 0 bottom
R6  10.0K  [0402]  150.21 83.37 270 bottom
R7  DNI  [0402]  143.48 83.82 270 bottom
R8  4.70K  [0402]  143.48 85.09 90 bottom
R9  4.70K  [0402]  150.09 151.76 180 bottom
R10  4.70K  [0402]  151.48 151.76 180 bottom
R11  4.70K  [0402]  152.88 151.76 180 bottom
R12  2.00K  [0402]  131.29 92.58 180 bottom
R13  10.0K  [0402]  150.21 87.18 270 bottom
R15  499  [0402]  154.67 76.2 270 top
R18  10.0K  [0402]  140.94 78.74 90 bottom
R19  1K  [0402]  140.94 77.47 90 bottom
R20  10.0K  [0402]  140.94 76.2 90 bottom
R21  10.0K  [0402]  143.48 77.34 90 bottom
R22  10.0K  [0402]  143.48 79.88 90 bottom
R23  DNI  [0402]  102.67 89.1 0 bottom
R24  DNI  [0402]  103.53 81.6 180 bottom
R25  DNI  [0402]  103.53 86.6 0 bottom
R26  DNI  [0402]  105.27 89.6 0 bottom
R27  10.0K  [0402]  102.08 79.25 180 bottom
R28  10.0K  [0402]  78.46 34.16 90 bottom
R29  10.0K  [0402]  103.1 79.25 180 bottom
R30  10.0K  [0402]  78.46 35.18 90 bottom
R31  10.0K  [0402]  105.51 87.38 270 bottom
R32  10.0K  [0402]  163.8 34.29 90 top
R33  0  [0402]  132.52 7.18 180 top
R34  10.0K  [0402]  105.51 86.49 270 bottom
R35  0  [0402]  93.66 8.19 180 top
R36  10.0K  [0402]  163.8 33.02 90 top
R37  DNI  [0402]  105.34 84.6 0 bottom
R38  DNI  [0402]  93.22 6.73 270 top
R39  10.0K  [0402]  106.78 84.96 270 bottom
R40  4.22K  [0402]  101.32 89.66 270 bottom
R41  10.0K  [0402]  194.92 57.02 90 top
R42  10.0K  [0402]  32 11.94 90 bottom
R43  0  [0402]  131.64 7.18 180 top
R44  0  [0402]  92.77 8.19 180 top
R45  10.0K  [0402]  106.78 84.07 270 bottom
R46  4.22K  [0402]  101.32 88.77 270 bottom
R47  10.0K  [0402]  194.92 56.01 90 top
R48  10.0K  [0402]  32 13.21 90 bottom
R49  DNI  [0402]  106.65 89.92 270 bottom
R50  DNI  [0402]  131.57 9.78 180 top
R51  DNI  [0402]  106.65 89.03 270 bottom
R52  DNI  [0402]  132.59 9.78 180 top
R53  240  [0402]  118.26 86.13 180 bottom
R54  DNI  [0402]  117.35 86.61 0 bottom
R55  10.0K  [0402]  127.71 49.12 180 bottom
R56  10.0K  [0402]  163.8 29.21 90 top
R57  10.0K  [0402]  128.9 49.12 180 bottom
R58  10.0K  [0402]  163.8 27.94 90 top
R59  DNI  [0402]  134.97 76.96 180 bottom
R60  51  [0402]  129.13 86.36 60 bottom
R61  DNI  [0402]  134.11 80.01 0 bottom
R62  120  [0402]  128.24 89.28 300 bottom
R63  240  [0402]  92.27 117.1 0 bottom
R64  DNI  [0402]  93.14 116.6 180 bottom
R65  10.0K  [0402]  70.81 107.34 90 bottom
R66  10.0K  [0402]  59.15 111.33 270 bottom
R67  10.0K  [0402]  70.84 105.87 90 bottom
R68  10.0K  [0402]  59.15 110.06 270 bottom
R69  DNI  [0402]  116.43 114.43 180 bottom
R70  120  [0402]  117.45 114.68 0 bottom
R71  DNI  [0402]  128.62 114.43 180 bottom
R72  120  [0402]  129.51 114.43 0 bottom
R73  10.0K  [0402]  40.39 146.3 0 top
R74  DNI  [0402]  39.62 158.62 180 top
R75  DNI  [0402]  46.86 146.3 0 top
R76  DNI  [0402]  46.35 158.5 180 top
R77  DNI  [0402]  42.16 158.62 180 top
R79  10.0K  [0402]  41.78 146.3 0 top
R80  10.0K  [0402]  45.21 158.5 180 top
R81  10.0K  [0402]  45.47 146.3 0 top
R82  DNI  [0402]  47.75 158.5 0 top
R83  DNI  [0402]  48.26 146.3 180 top
R84  DNI  [0402]  40.89 158.62 0 top
R85  2.0K  [0402]  101.37 105.85 300 bottom
R86  2.80K  [0402]  121.72 97.1 0 bottom
R87  169  [0402]  126.92 99.1 180 bottom
R88  DNI  [0402]  146.38 79.5 270 bottom
R89  1.00K  [0402]  143.48 78.61 270 bottom
R92  0  [0402]  124.21 94.11 90 bottom
R93  DNI  [0402]  131.34 33.09 270 bottom
R94  0  [0402]  68.2 94.74 90 bottom
R95  0  [0402]  68.2 96.01 90 bottom
R96  0  [0402]  98.07 91.47 90 bottom
R97  0  [0402]  98.07 92.41 90 bottom
R98  2.0K  [0402]  95.27 75.82 270 bottom
R99  2.0K  [0402]  93.7 75.36 180 bottom
R102  3.3K  [0402]  77.82 58.04 0 bottom
R103  3.3K  [0402]  79.09 58.04 0 bottom
R104  DNI  [0402]  128.32 55.14 180 bottom
R105  4.7K  [0402]  77.82 63.5 0 bottom
R106  4.7K  [0402]  79.09 63.5 0 bottom
R107  3.3K  [0402]  149.32 207.47 90 bottom
R108  DNI  [0402]  81.51 63.5 0 bottom
R109  DNI  [0402]  129.51 52.96 90 bottom
R110  DNI  [0402]  130.07 51.55 0 bottom
R111  DNI  [0402]  128.62 58.42 270 bottom
R112  DNI  [0402]  129.64 55.12 0 bottom
R113  0  [0402]  91.07 52.46 180 bottom
R114  0  [0402]  89.94 52.46 180 bottom
R115  0  [0402]  113.08 55.02 0 bottom
R116  240  [0402]  83.82 145.8 0 bottom
R117  240  [0402]  95.25 145.8 0 bottom
R118  0  [0402]  84.07 144.15 90 bottom
R119  0  [0402]  95.5 144.15 90 bottom
R120  240  [0402]  106.68 145.8 0 bottom
R121  240  [0402]  118.11 145.49 0 bottom
R122  0  [0402]  106.91 144.12 90 bottom
R123  0  [0402]  118.24 144.15 90 bottom
R124  1K  [0402]  78.87 139.83 90 bottom
R125  1K  [0402]  73.89 141.22 0 bottom
R126  1K  [0402]  76.83 142.88 270 bottom
R127  1K  [0402]  76.71 141.86 90 bottom
R128  1K  [0402]  79.12 142.57 270 bottom
R129  1K  [0402]  73.51 142.49 270 bottom
R130  1K  [0402]  77.09 144.4 180 bottom
R131  1K  [0402]  75.11 143.32 270 bottom
R132  1K  [0402]  79.12 144.07 270 bottom
R133  1K  [0402]  76.68 140.84 90 bottom
R134  1K  [0402]  74.8 139.83 270 bottom
R135  240  [0402]  71.75 144.91 0 bottom
R136  0  [0402]  73.51 144.11 270 bottom
R137  36  [0402]  129.13 151 90 top
R138  49.9  [0402]  129.13 151.89 90 top
R139  DNI  [0402]  129.13 154.56 90 bottom
R140  1K  [0402]  129.13 154.56 270 top
R141  DNI  [0402]  129.13 150.11 90 bottom
R142  1K  [0402]  129.13 144.65 270 top
R143  100  [0402]  129.13 150.11 90 top
R144  DNI  [0402]  129.13 144.65 270 bottom
R145  36  [0402]  120.88 148.06 270 bottom
R146  36  [0402]  119.1 148.06 90 bottom
R178  0  [0402]  161.26 85.85 90 top
R179  0  [0402]  163.93 84.33 0 bottom
R180  10.0K  [0402]  44.55 183.51 180 top
R181  10.0K  [0402]  39.22 183.51 180 top
R182  10.0K  [0402]  180.82 91.19 90 bottom
R183  10.0K  [0402]  182.04 118.57 90 bottom
R189  DNI  [0402]  65.99 81.97 90 bottom
R190  1M  [1206]  10.23 53.77 270 bottom
R191  DNI  [0402]  54.48 57.4 0 bottom
R192  DNI  [0402]  53.21 57.4 0 bottom
R193  DNI  [0402]  55.75 57.4 0 bottom
R194  4.7K  [0402]  63.63 85.72 90 bottom
R195  4.7K  [0402]  63.63 82.68 90 bottom
R196  3.3K  [0402]  53.59 83.44 270 bottom
R197  4.7K  [0402]  63.63 81.66 90 bottom
R198  3.3K  [0402]  53.59 82.17 270 bottom
R199  4.7K  [0402]  62.84 83.69 90 bottom
R200  DNI  [0402]  62.84 84.71 270 bottom
R201  4.7K  [0402]  53.59 84.71 270 top
R202  4.7K  [0402]  58.01 83.95 90 top
R203  4.7K  [0402]  58.01 82.93 90 top
R204  DNI  [0402]  51.94 57.4 0 bottom
R205  DNI  [0402]  48.23 57.4 0 bottom
R206  DNI  [0402]  49.5 57.4 0 bottom
R207  4.7K  [0402]  69.09 86.11 90 top
R208  DNI  [0402]  50.67 57.4 0 bottom
R209  4.7K  [0402]  69.09 84.07 90 top
R210  4.7K  [0402]  69.09 83.06 90 top
R211  4.7K  [0402]  69.09 85.09 90 top
R212  4.7K  [0402]  58.01 85.09 90 top
R213  4.7K  [0402]  69.06 92.71 90 top
R214  4.7K  [0402]  69.06 91.69 90 top
R215  4.7K  [0402]  69.06 90.68 90 top
R216  4.7K  [0402]  58.01 91.44 90 top
R217  4.7K  [0402]  69.06 89.53 90 top
R218  10.0K  [0402]  64.36 93.15 180 bottom
R219  10.0K  [0402]  62 92.35 270 bottom
R220  10.0K  [0402]  64.14 89.41 270 bottom
R221  10.0K  [0402]  53.21 92.46 270 bottom
R222  10.0K  [0402]  64.14 88.39 270 bottom
R223  DNI  [0402]  62 91.29 270 bottom
R224  10.0K  [0402]  53.72 90.04 90 bottom
R225  10.0K  [0402]  53.72 89.03 90 bottom
R226  4.7K  [0402]  58.01 90.42 90 top
R227  4.7K  [0402]  58.01 89.41 90 top
R228  DNI  [0402]  66.75 88.39 180 bottom
R229  1M  [1206]  13.82 109.35 90 bottom
R230  1K  [0402]  201.9 19.05 270 bottom
R231  10.0K  [0402]  201.9 20.32 270 bottom
R232  10.0K  [0402]  201.9 21.59 270 bottom
R233  10.0K  [0402]  201.9 22.86 270 bottom
R234  DNI  [0402]  199.01 28.7 270 top
R235  0  [0402]  212.6 19.56 270 top
R236  0  [0402]  212.6 20.83 270 top
R237  10.0K  [0402]  212.6 23.62 270 top
R238  4.7K  [0402]  199.01 27.3 90 top
R239  10.0K  [0402]  212.6 26.16 270 top
R240  10.0K  [0402]  43.41 183.51 0 top
R241  4.7K  [0402]  32 22.61 90 top
R242  4.7K  [0402]  32 21.34 90 top
R243  4.7K  [0402]  32 20.07 90 top
R244  4.7K  [0402]  32 18.8 90 top
R245  4.7K  [0402]  37.21 22.61 270 top
R246  4.7K  [0402]  37.21 21.34 270 top
R247  4.7K  [0402]  37.21 20.07 270 top
R248  4.7K  [0402]  37.21 18.8 270 top
R249  0  [0402]  23.62 22.23 0 top
R250  0  [0402]  25.53 22.23 0 top
R251  DNI  [0402]  34.04 17.65 0 top
R252  10.0K  [0402]  20.08 6.29 90 bottom
R253  4.99K  [0402]  22.42 17.34 90 bottom
R254  4.7K  [0402]  20.12 11.51 0 bottom
R255  49.9  [0402]  17.53 18.8 90 top
R256  49.9  [0402]  17.53 17.53 90 top
R257  49.9  [0402]  17.53 16.26 90 top
R258  49.9  [0402]  17.53 14.99 90 top
R259  49.9  [0402]  17.53 13.72 90 top
R260  49.9  [0402]  17.53 12.45 90 top
R261  49.9  [0402]  17.53 11.18 90 top
R262  49.9  [0402]  17.53 9.91 90 top
R263  160  [0402]  25.99 8.74 90 bottom
R264  160  [0402]  29.18 8.8 270 bottom
R265  160  [0402]  32.35 8.76 270 bottom
R266  160  [0402]  35.58 8.77 270 bottom
R267  160  [0402]  38.72 8.76 270 bottom
R269  4.7K  [0402]  155.45 149.99 0 bottom
R270  4.7K  [0402]  156.72 149.99 0 bottom
R271  4.7K  [0402]  157.99 149.99 0 bottom
R272  1.00K  [0402]  157.99 145.03 180 bottom
R273  1.00K  [0402]  156.72 145.03 180 bottom
R274  1.00K  [0402]  155.45 145.03 180 bottom
R275  10.0K  [0402]  136.91 194.94 180 bottom
R276  10.0K  [0402]  141.35 194.94 180 bottom
R277  10.0K  [0402]  145.8 194.94 180 bottom
R278  10.0K  [0402]  150.09 194.88 180 bottom
R279  4.7K  [0402]  155.07 147.57 90 bottom
R280  10.0K  [0402]  154.69 194.94 180 bottom
R281  10.0K  [0402]  159.13 194.94 180 bottom
R282  10.0K  [0402]  163.58 194.94 180 bottom
R283  10.0K  [0402]  168.02 194.94 180 bottom
R284  422.00  [0402]  184.28 214 0 bottom
R285  422.00  [0402]  180.97 214.12 0 bottom
R286  422.00  [0402]  177.67 214.12 0 bottom
R287  422.00  [0402]  174.37 214.12 0 bottom
R288  422.00  [0402]  171.07 214.88 180 bottom
R289  422.00  [0402]  167.77 214.91 180 bottom
R290  422.00  [0402]  164.47 214.86 180 bottom
R291  422.00  [0402]  161.16 214.88 180 bottom
R292  0  [0402]  18.82 170.25 180 bottom
R293  0  [0402]  20.85 170.25 0 top
R294  10.0K  [0402]  33.75 154.56 90 bottom
R295  100K  [0402]  29.44 180.21 180 top
R296  2.00K  [0402]  18.82 170.25 0 top
R297  2.00K  [0402]  19.84 170.25 0 top
R298  1M  [1206]  12.47 163.49 0 bottom
R299  10.0K  [0402]  16.25 173.1 90 top
R300  20.0K  [0402]  16.25 174.14 90 top
R301  0  [0402]  47.6 175.39 90 bottom
R302  10.0K  [0402]  30.45 166.75 0 bottom
R303  0  [0402]  18.03 162.05 180 bottom
R304  0  [0402]  18.03 157.48 180 bottom
R305  0  [0402]  18.03 167.13 180 bottom
R306  0  [0402]  18.03 159.64 180 bottom
R307  10.0K  [0402]  42.42 170.21 270 bottom
R308  10.0K  [0402]  42.39 171.25 270 bottom
R309  10.0K  [0402]  29.97 156.72 0 bottom
R310  10.0K  [0402]  16.76 157.48 180 bottom
R311  10.0K  [0402]  16.76 162.05 180 bottom
R312  10.0K  [0402]  16.76 167.13 180 bottom
R313  49.9  [0402]  30.1 132.59 180 bottom
R314  49.9  [0402]  40.39 132.61 180 bottom
R315  49.9  [0402]  31.37 135.13 180 bottom
R316  49.9  [0402]  41.66 135.13 180 bottom
R317  49.9  [0402]  31.37 132.59 180 bottom
R318  49.9  [0402]  41.66 132.61 180 bottom
R319  49.9  [0402]  32.64 135.13 180 bottom
R320  49.9  [0402]  42.93 135.13 180 bottom
R321  49.9  [0402]  33.91 132.59 180 bottom
R322  49.9  [0402]  42.93 132.61 180 bottom
R323  49.9  [0402]  33.91 135.13 180 bottom
R324  49.9  [0402]  44.2 135.13 180 bottom
R325  49.9  [0402]  35.18 132.59 180 bottom
R326  49.9  [0402]  44.2 132.61 180 bottom
R327  49.9  [0402]  35.18 135.13 180 bottom
R328  49.9  [0402]  45.47 135.13 180 bottom
R329  49.9  [0402]  36.45 132.59 180 bottom
R330  49.9  [0402]  45.47 132.61 180 bottom
R331  49.9  [0402]  36.45 135.13 180 bottom
R332  49.9  [0402]  46.74 135.13 180 bottom
R333  1.00K  [0402]  28.83 132.59 180 bottom
R334  1.00K  [0402]  40.39 135.13 180 bottom
R335  10.0K  [0402]  25.37 159.64 0 top
R336  10.0K  [0402]  24.18 159.64 0 top
R337  10.0K  [0402]  23.01 159.64 0 top
R338  10.0K  [0402]  26.57 159.64 0 top
R340  10.0K  [0402]  41.12 175.49 0 bottom
R341  10.0K  [0402]  46.99 180.97 0 bottom
R344  422.00  [0402]  139.42 213.99 0 bottom
R347  422.00  [0402]  136.37 213.99 0 bottom
R348  422.00  [0402]  142.49 214 0 bottom
R349  10.0K  [0402]  42.88 178.66 0 bottom
R350  10.0K  [0402]  47.62 176.4 270 bottom
R351  DNI  [0402]  42.29 183.51 180 top
R352  422.00  [0402]  145.54 214 0 bottom
R353  1K  [0402]  47.12 178.94 180 bottom
R354  DNI  [0402]  45.82 183.51 180 top
R355  DNI  [0402]  40.26 183.51 180 top
R356  DNI  [0402]  13.33 144.98 0 top
R357  DNI  [0402]  41.27 183.51 180 top
R358  100K  [0402]  29.47 167.77 0 top
R359  10.0K  [0402]  180.31 178.43 0 bottom
R363  422.00  [0402]  154.69 214 0 bottom
R364  422.00  [0402]  157.73 214 0 bottom
R367  422.00  [0402]  148.54 213.98 0 bottom
R368  422.00  [0402]  151.59 213.98 0 bottom
R371  10.0K  [0402]  161.26 83.31 90 top
R372  10.0K  [0402]  161.29 88.39 90 top
R373  10.0K  [0402]  161.29 89.66 90 top
R374  1.00K  [0402]  161.26 84.58 90 top
R375  10.0K  [0402]  161.29 87.27 270 top
R376  10.0K  [0402]  157.78 90.83 270 top
R377  10.0K  [0402]  161.29 96.29 270 top
R378  10.0K  [0402]  157.81 91.85 270 top
R380  4.7K  [0402]  162.56 96.14 90 bottom
R381  4.7K  [0402]  162.56 97.41 90 bottom
R382  4.7K  [0402]  162.56 98.68 90 bottom
R383  4.7K  [0402]  162.56 99.95 90 bottom
R384  10.0K  [0402]  169.26 153.86 0 bottom
R385  10.0K  [0402]  174.09 153.86 0 bottom
R386  10.0K  [0402]  183.23 153.86 0 bottom
R387  10.0K  [0402]  178.79 153.86 0 bottom
R388  422.00  [0402]  177.39 148.59 180 bottom
R389  422.00  [0402]  174.34 148.59 180 bottom
R390  422.00  [0402]  180.44 148.59 180 bottom
R391  422.00  [0402]  183.49 148.59 180 bottom
R394  422.00  [0402]  189.61 148.59 180 bottom
R395  422.00  [0402]  192.66 148.59 180 bottom
R396  DNI  [0402]  171.83 115.82 180 top
R397  DNI  [0402]  173.1 115.82 180 top
R398  4.7K  [0402]  175.26 114.55 90 top
R399  4.7K  [0402]  175.26 112.01 90 top
R400  4.7K  [0402]  175.26 109.47 90 top
R401  0  [0402]  193.45 136.63 0 bottom
R402  DNI  [0805]  188.21 131.95 180 bottom
R403  DNI  [0402]  12.57 114.17 0 bottom
R404  DNI  [0805]  14.53 113.94 180 bottom
R405  0  [0402]  41.27 45.34 270 bottom
R406  1K  [0402]  15.88 48.41 180 bottom
R407  100  [0402]  17.14 48.41 180 bottom
R408  1K  [0402]  18.8 52.32 270 bottom
R409  DNI  [0402]  63.25 23.66 270 top
R410  100  [0402]  90.78 36.04 0 bottom
R411  100  [0402]  90.78 34.04 180 bottom
R412  DNI  [0402]  94.59 37.34 180 bottom
R413  0  [0402]  82.3 34.16 270 bottom
R414  0  [0402]  82.3 35.18 270 bottom
R415  DNI  [0402]  86.33 30.73 0 bottom
R416  0  [0402]  82.3 36.45 270 bottom
R417  1K  [0402]  85.19 30.73 0 bottom
R418  0  [0402]  82.3 37.47 270 bottom
R419  1K  [0402]  84.15 30.76 0 bottom
R420  0  [0402]  86.47 39.12 180 bottom
R421  0  [0402]  87.49 39.12 180 bottom
R422  DNI  [0402]  84.96 42.42 180 bottom
R423  0  [0402]  102.97 34.04 270 bottom
